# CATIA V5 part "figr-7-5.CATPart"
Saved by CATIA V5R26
Part number: Part1
Bounding box of the stored display mesh (mm): x 0 to 95, y -20 to 20, z 0 to 40
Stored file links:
  D:\_Deepak\CATIA\CATIA V5-6R2016_Deepak\Resources\Part files\Partfiles\c07_catia_v5_6r2016_prt\figr-7-5.CATPart
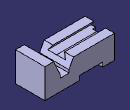
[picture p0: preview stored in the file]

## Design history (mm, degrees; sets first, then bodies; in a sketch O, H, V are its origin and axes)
Body1 (main body)
  Sketch1 on zx-plane, origin (0, 0, 0), H (-1, 0, 0), V (0, 0, 1)
    line L1 (0, 0) -> (-16, 0)
    line L2 (-16, 0) -> (-16, 6)
    line L3 (-16, 6) -> (-48, 6)
    line L4 (-48, 6) -> (-48, 0)
    point P4 (-48, 0)
    line L5 (-48, 0) -> (-95, 0)
    line L6 (-95, 0) -> (-95, 40)
    line L7 (-95, 40) -> (-83, 40)
    line L8 (-83, 40) -> (-74, 20)
    line L9 (-74, 20) -> (-74, 16)
    line L10 (-74, 16) -> (-62, 16)
    line L11 (-62, 16) -> (-62, 20)
    line L12 (-62, 20) -> (-56, 32)
    line L13 (-56, 32) -> (0, 32)
    line L14 (0, 32) -> (0, 0)
    length L1 = 16
    length L3 = 32
    length L13 = 56
    distance L14 L6 = 95
    length L14 = 32
    length L6 = 40
    length L12 H = 6
    length L10 = 12
    length L7 = 12
    length L9 = 4
    length L2 = 6
    distance L10 L5 = 16
    length L12 V = 12
    horizontal: L1 H, L3 H, L5 H, L7 H, L10 H, L13 H
    vertical: L2 V, L4 V, L6 V, L9 V, L11 V, L14 V
    coincidence: P4 H
  Pad1: profile Sketch1, direction (0, 1, 0), length 20, mirrored extent
  Sketch2 on face of Pad1, origin (0, 0, 0), H (0, -1, 0), V (0, 0, 1)
    axis line L1 (0, 0) -> (0, 40.9766)
    point P2 (0, 32)
    line L2 (0, 32) -> (-8, 32)
    point P3 (-8, 32)
    line L3 (-8, 32) -> (-12, 26)
    point P4 (-12, 26)
    line L4 (-12, 26) -> (0, 26)
    point P5 (0, 26)
    reference projected line E1 (-20, 32) -> (20, 32) from edge [face of Pad1 | face of Pad1]
    point P6 (0, 32)
    point P7 (8, 32)
    point P8 (12, 26)
    point P9 (0, 26)
    line L5 (0, 32) -> (8, 32)
    line L6 (8, 32) -> (12, 26)
    line L7 (12, 26) -> (0, 26)
    reference projected line E2 (-20, 0) -> (-20, 32) from edge [face of Pad1 | face of Pad1]
    reference projected line E3 (-20, 20) -> (-20, 40) from edge [face of Pad1 | face of Pad1]
    distance P4 E2 = 8
    length L3 V = 6
    distance P3 E3 = 12
    vertical: L1 V
    coincidence: P2 L1, P5 L1, L2 E1, P2 P6, P5 P9
    horizontal: L2 H, L4 H
    symmetry: P2 P6 L1, P3 P7 L1, P4 P8 L1, P5 P9 L1, L2 L5 L1, L3 L6 L1, L4 L7 L1
  Pocket1: profile Sketch2, direction (1, 0, 0), through (limit type 6)
  Sketch3 on face of Pad1, origin (0, 0, 0), H (0, -1, 0), V (0, 0, 1)
    line L1 (-6, 0) -> (6, 0)
    line L2 (6, 0) -> (6, 26)
    line L3 (6, 26) -> (-6, 26)
    line L4 (-6, 26) -> (-6, 0)
    reference projected line E1 (-12, 26) -> (0, 26) from edge [face of Pad1 | face of Pocket1]
    length L1 = 12
    horizontal: L1 H, L3 H
    vertical: L2 V, L4 V
    midpoint: O L1
    coincidence: L3 E1
  Pocket2: profile Sketch3, direction (1, 0, 0), length 4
